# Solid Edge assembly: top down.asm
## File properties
Title: Yoke
Author: Deepak Maini
Template: normal.par
Last saved by: CADCIM
Revision: 21
Application: Solid Edge
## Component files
u-joint.par
swivel.par
bushing1.par
ret ring.par
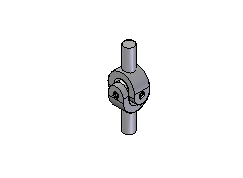
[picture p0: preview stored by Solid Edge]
